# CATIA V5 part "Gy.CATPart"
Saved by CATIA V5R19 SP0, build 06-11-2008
Part number: Gy
Publications: "L", "H", "P", "e"
Bounding box of the stored display mesh (mm): x -600 to 0, y 0 to 105, z -100 to 100
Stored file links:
  G:\EU_thinkMotion\CFAO_2010\MMS_groupe3\MMS_groupe3\A reprendre\evulliez\evulliez\Gy.CATPart
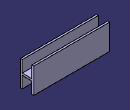
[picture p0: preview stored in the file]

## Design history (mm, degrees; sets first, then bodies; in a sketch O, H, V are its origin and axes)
Parameters
  L = 600 mm
  H = 105 mm
  P = 200 mm
  e = 15 mm
Body1 (main body)
  Sketch1 on yz-plane, origin (0, 0, 0), H (0, 1, 0), V (0, 0, 1)
    line L1 (15, -7.5) -> (15, -100)
    point P1 (15, -7.5)
    point P2 (15, -100)
    line L2 (15, -7.5) -> (52.5, -7.5)
    point P3 (52.5, -7.5)
    line L3 (15, -100) -> (0, -100)
    point P4 (0, -100)
    point P5 (15, 7.5)
    point P6 (15, 100)
    point P7 (52.5, 7.5)
    point P8 (0, 100)
    line L4 (15, 7.5) -> (15, 100)
    line L5 (15, 7.5) -> (52.5, 7.5)
    line L6 (15, 100) -> (0, 100)
    line L7 (0, 100) -> (0, -100)
    line L8 (52.5, 7.5) -> (52.5, -7.5)
    distance H L2 = 7.5 {= e /2}
    distance V L1 = 15 {= e}
    length L1 = 92.5 {= (P -e )/2}
    length L2 = 37.5 {= H /2 -e}
    length L3 = 15 {= e}
    vertical: L1 V, L7 V, L8 V
    horizontal: L2 H, L3 H
    symmetry: P1 P5 H, P2 P6 H, P3 P7 H, P4 P8 H, L1 L4 H, L2 L5 H, L3 L6 H
  Pad1: profile Sketch1, direction (-1, 0, 0), length 600 {= L}
  Mirror1: of Pad1, about face of Pad1 from Sketch1.L8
